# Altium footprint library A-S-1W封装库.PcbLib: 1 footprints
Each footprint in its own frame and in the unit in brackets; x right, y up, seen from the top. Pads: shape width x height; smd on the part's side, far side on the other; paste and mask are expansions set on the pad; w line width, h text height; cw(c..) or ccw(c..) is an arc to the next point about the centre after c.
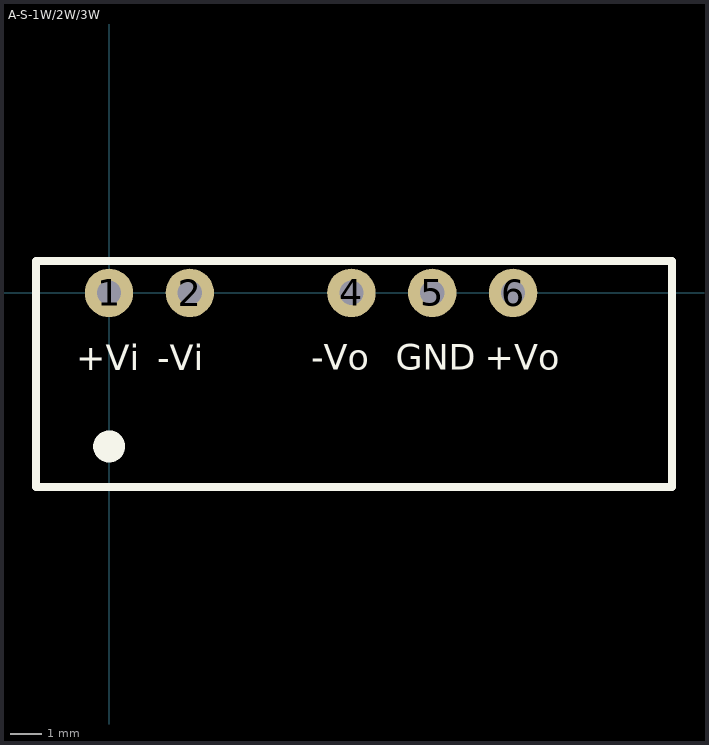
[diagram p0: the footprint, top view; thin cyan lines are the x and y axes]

## A-S-1W/2W/3W [mil]
pads (5):
  round 60 hole 30: 1(0,0) 2(100,0) 4(300,0) 5(400,0) 6(500,0)
Top Overlay:
  circle w19.68: c0.16,-190 r9.84
  lines w10: -90.55,-240.16 -90.55,39.37 696.85,39.37 696.85,-240.16 -90.55,-240.16
  text "GND" at 355,-95 h31.5
  text "+Vi" at -40.55,-95.63 h31.5
  text "-Vi" at 59.45,-95.63 h31.5
  text "-Vo" at 250,-95 h31.5
  text "+Vo" at 465,-95 h31.5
